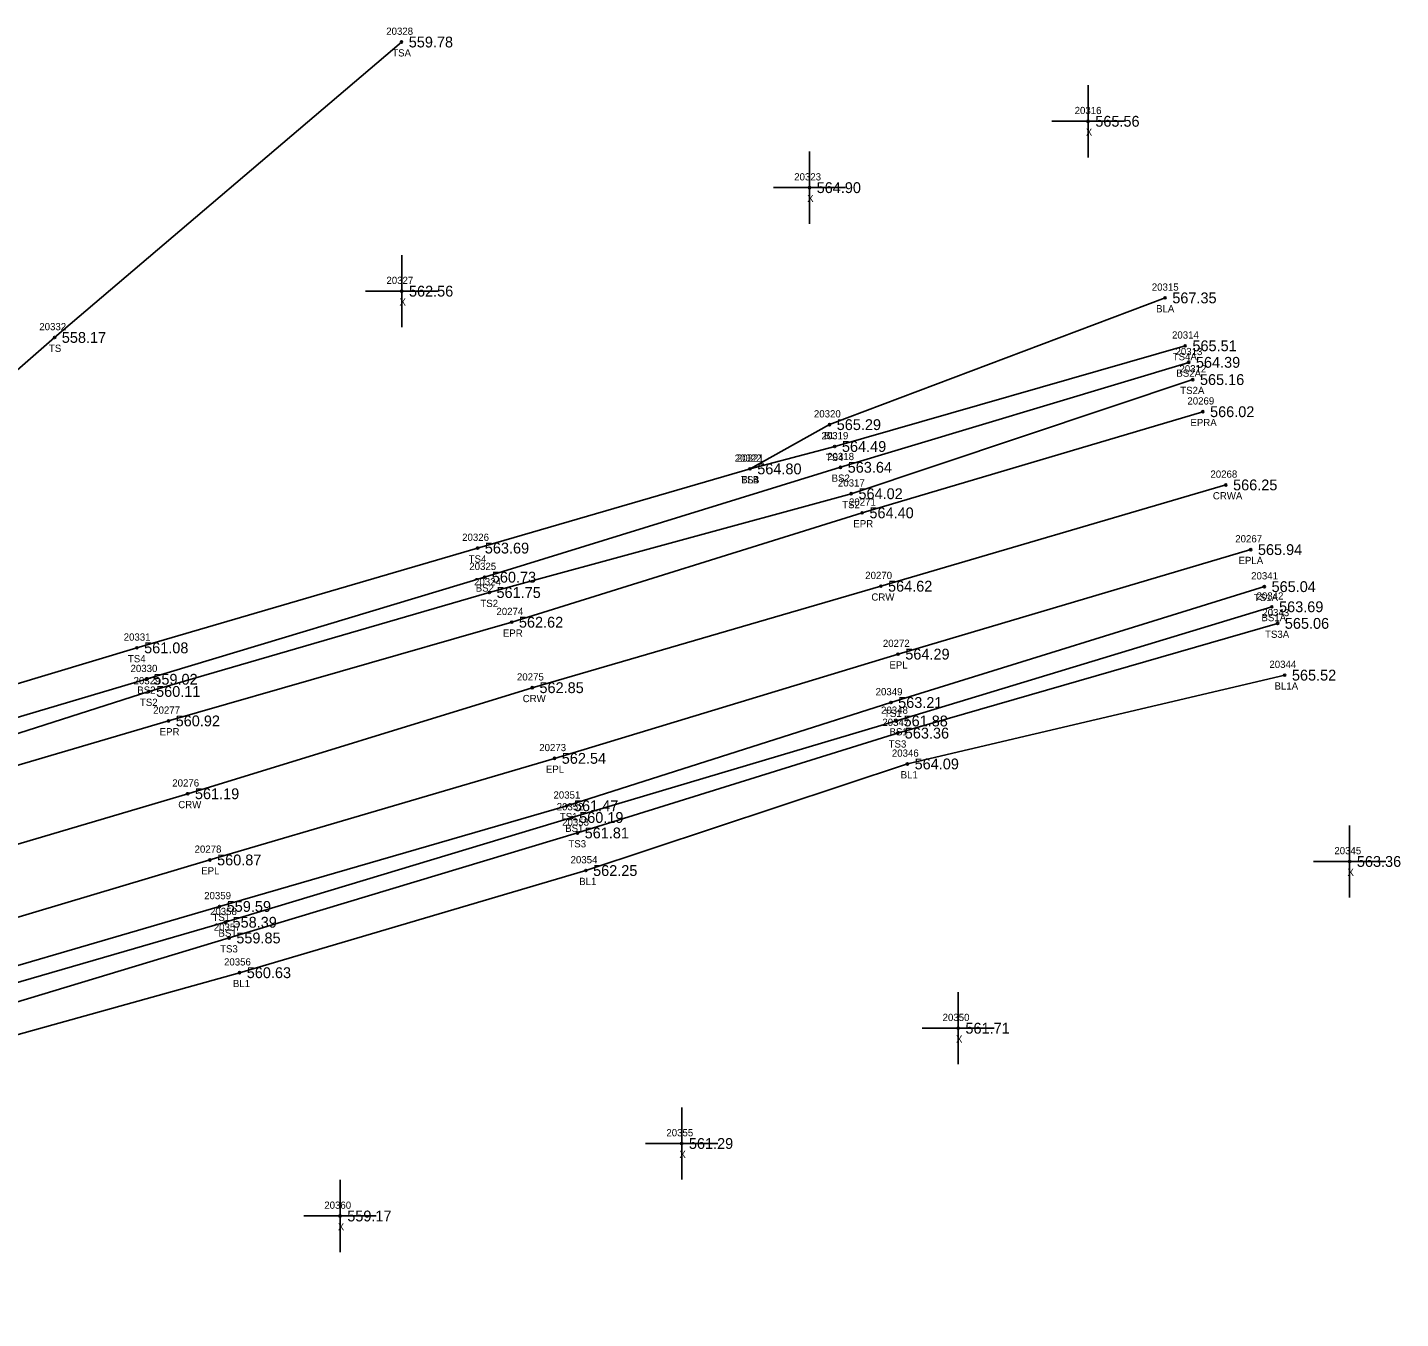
# Model space of a CAD drawing. Extents: x 1540443 to 1541844, y 887157 to 888162.
# Drawn here: x 1541653.6 to 1541843.8, y 887763.6 to 887942.4 of the extents above; entities that cross this region are included whole.
import ezdxf

# ---------------------------------------------------------------- set-up
doc = ezdxf.new("R2010")
doc.units = 0
for name, color, linetype in [('RD_DTM_BkLn1', 7, 'Continuous'), ('RD_DTM_BkLn2', 7, 'Continuous'), ('RD_DTM_BkLn_txCode', 7, 'Continuous'), ('RD_EX_Misc', 7, 'Continuous'), ('RD_EX_Misc_txCode', 7, 'Continuous'), ('RD_EX_Road', 7, 'Continuous'), ('RD_EX_Road_txCode', 7, 'Continuous'), ('RD_EX_TX_Misc_ELEV', 7, 'Continuous'), ('RD_EX_TX_Road_ELEV', 7, 'Continuous'), ('RD_HC_Survey_ELEV', 7, 'Continuous'), ('RD_HC_Survey_txCode', 7, 'Continuous'), ('RD_SMD_Locator', 7, 'Continuous')]:
    doc.layers.add(name, color=color, linetype=linetype)

msp = doc.modelspace()

# ---------------------------------------------------------------- linework, layer by layer
at = {"layer": 'RD_DTM_BkLn1'}
for points in [[(1541811.22, 887904.95), (1541764.73, 887887.39), (1541753.72, 887881.26)], [(1541819.64, 887879.04), (1541771.84, 887865.01), (1541723.55, 887850.95), (1541675.82, 887836.26), (1541627.89, 887822.08), (1541580.01, 887807.87), (1541531.93, 887793.38), (1541484.13, 887778.91), (1541435.66, 887765.21), (1541388.1, 887751.04), (1541339.55, 887736.89), (1541291.46, 887723.08), (1541243.5, 887708.82), (1541195.27, 887694.78), (1541169.43, 887686.85)], [(1541827.79, 887852.69), (1541775.52, 887840.39), (1541730.98, 887825.62), (1541683, 887811.47), (1541633.73, 887797.72), (1541590.59, 887782.42), (1541539.36, 887766.46)]]:
    msp.add_lwpolyline(points, dxfattribs=at)
at = {"layer": 'RD_DTM_BkLn2'}
for points in [[(1541705.44, 887940.39), (1541657.38, 887899.47), (1541615.37, 887862.76), (1541586.87, 887843.69), (1541555.2, 887844), (1541525.74, 887837.02), (1541487.41, 887823.68), (1541473.12, 887820.98), (1541413.13, 887806.68)], [(1541814.01, 887898.31), (1541765.45, 887884.36), (1541753.72, 887881.26), (1541715.98, 887870.29), (1541668.78, 887856.47), (1541621.42, 887842.24), (1541577.85, 887827.54), (1541526.45, 887812.7), (1541478.33, 887797.72), (1541429.46, 887781.77)], [(1541814.49, 887896.02), (1541766.25, 887881.48), (1541716.95, 887866.26), (1541670.06, 887852.12), (1541622.59, 887838.05), (1541578.09, 887825.05), (1541526.96, 887809.73), (1541478.59, 887795.12), (1541429.46, 887781.77), (1541395.42, 887775.23), (1541380.33, 887789.16)], [(1541815.05, 887893.63), (1541767.74, 887877.82), (1541717.6, 887864.13), (1541670.44, 887850.43), (1541623.55, 887835.4), (1541578.57, 887823.06), (1541527.24, 887806.39), (1541479.99, 887791.81), (1541430.31, 887778.05), (1541393.69, 887768.38), (1541380.33, 887789.16)], [(1541824.97, 887864.95), (1541773.24, 887848.9), (1541728.33, 887834.59), (1541680.22, 887820.65), (1541632.2, 887806.6), (1541586.15, 887794.2), (1541535.56, 887777.78), (1541490.03, 887763.87), (1541442.11, 887749.28), (1541414.74, 887732.66), (1541394.55, 887728.51), (1541346.01, 887715.56), (1541298.68, 887704.05), (1541256.52, 887687.99), (1541253.67, 887682.12), (1541204.18, 887671.81), (1541185.24, 887668.7), (1541173.43, 887674.53)], [(1541826.01, 887862.16), (1541773.99, 887846.34), (1541729.05, 887832.97), (1541681.03, 887818.46), (1541632.94, 887804.51), (1541587.44, 887789.41), (1541536.78, 887773.27), (1541491.06, 887758.08), (1541445.99, 887740.14), (1541416.24, 887728.45), (1541395.49, 887723.75), (1541347.04, 887711.22), (1541300.85, 887696.02), (1541261.64, 887680.26), (1541255.59, 887675.42), (1541206.42, 887663.07), (1541174, 887652.79)], [(1541826.81, 887859.86), (1541774.16, 887844.66), (1541729.81, 887830.83), (1541681.55, 887816.28), (1541633.12, 887801.68), (1541588.74, 887788.35), (1541537.56, 887771.08), (1541491.43, 887756.24), (1541446.51, 887737.74), (1541416.24, 887728.45)]]:
    msp.add_lwpolyline(points, dxfattribs=at)
at = {"layer": 'RD_EX_Misc'}
for p, q in [((1541800.55, 887924.41), (1541800.55, 887934.41)), ((1541795.55, 887929.41), (1541805.55, 887929.41)), ((1541761.95, 887915.22), (1541761.95, 887925.22)), ((1541756.95, 887920.22), (1541766.95, 887920.22)), ((1541705.47, 887900.88), (1541705.47, 887910.88)), ((1541700.47, 887905.88), (1541710.47, 887905.88)), ((1541836.79, 887821.88), (1541836.79, 887831.88)), ((1541831.79, 887826.88), (1541841.79, 887826.88)), ((1541782.56, 887798.78), (1541782.56, 887808.78)), ((1541777.56, 887803.78), (1541787.56, 887803.78)), ((1541744.25, 887782.81), (1541744.25, 887792.81)), ((1541739.25, 887787.81), (1541749.25, 887787.81)), ((1541696.92, 887772.77), (1541696.92, 887782.77)), ((1541691.92, 887777.77), (1541701.92, 887777.77))]:
    msp.add_line(p, q, dxfattribs=at)
at = {"layer": 'RD_EX_Road'}
for points in [[(1541816.45, 887889.18), (1541769.26, 887875.17), (1541720.7, 887860.02), (1541673.15, 887846.35), (1541624.52, 887832.03), (1541577.1, 887817.68), (1541529.45, 887803.59), (1541481.09, 887788.89), (1541433.23, 887775.3), (1541384.84, 887760.56), (1541337.12, 887746.96), (1541288.35, 887732.65), (1541241.37, 887718.72), (1541192.23, 887703.89), (1541166.88, 887695.38)], [(1541823.08, 887870.08), (1541774.23, 887855.6), (1541726.64, 887841.16), (1541678.89, 887827.09), (1541630.15, 887812.57), (1541582.93, 887798.43), (1541534.59, 887784.1), (1541487.04, 887769.99), (1541438.64, 887755.66), (1541391.44, 887742.05), (1541342.36, 887727.48), (1541295.07, 887713.91), (1541246.74, 887699.66), (1541197.81, 887684.79), (1541172.48, 887676.63)]]:
    msp.add_lwpolyline(points, dxfattribs=at)
at = {"layer": 'RD_SMD_Locator'}
for centre in [(1541705.44, 887940.39), (1541800.55, 887929.41), (1541761.95, 887920.22), (1541705.47, 887905.88), (1541811.22, 887904.95), (1541657.38, 887899.47), (1541814.01, 887898.31), (1541814.49, 887896.02), (1541815.05, 887893.63), (1541816.45, 887889.18), (1541764.73, 887887.39), (1541765.45, 887884.36), (1541753.72, 887881.26), (1541753.72, 887881.26), (1541766.25, 887881.48), (1541819.64, 887879.04), (1541767.74, 887877.82), (1541769.26, 887875.17), (1541715.98, 887870.29), (1541823.08, 887870.08), (1541716.95, 887866.26), (1541771.84, 887865.01), (1541824.97, 887864.95), (1541717.6, 887864.13), (1541826.01, 887862.16), (1541720.7, 887860.02), (1541826.81, 887859.86), (1541668.78, 887856.47), (1541774.23, 887855.6), (1541670.06, 887852.12), (1541827.79, 887852.69), (1541670.44, 887850.43), (1541723.55, 887850.95), (1541773.24, 887848.9), (1541673.15, 887846.35), (1541773.99, 887846.34), (1541774.16, 887844.66), (1541726.64, 887841.16), (1541775.52, 887840.39), (1541675.82, 887836.26), (1541728.33, 887834.59), (1541729.05, 887832.97), (1541729.81, 887830.83), (1541678.89, 887827.09), (1541730.98, 887825.62), (1541836.79, 887826.88), (1541680.22, 887820.65), (1541681.03, 887818.46), (1541681.55, 887816.28), (1541683, 887811.47), (1541782.56, 887803.78), (1541744.25, 887787.81), (1541696.92, 887777.77)]:
    msp.add_circle(centre, 0.15, dxfattribs=at)

# ---------------------------------------------------------------- texts
at = {"layer": 'RD_DTM_BkLn_txCode'}
for s, p in [('20328', (1541703.32, 887941.39)), ('TSA', (1541704.15, 887938.39)), ('20315', (1541809.38, 887905.95)), ('BLA', (1541809.97, 887902.95)), ('20332', (1541655.26, 887900.47)), ('20314', (1541812.18, 887899.31)), ('TS', (1541656.59, 887897.47)), ('20313', (1541812.66, 887897.02)), ('TS4A', (1541812.28, 887896.31)), ('20312', (1541813.21, 887894.63)), ('BS2A', (1541812.78, 887894.02)), ('TS2A', (1541813.32, 887891.63)), ('20320', (1541762.57, 887888.39)), ('20319', (1541763.62, 887885.36)), ('BL', (1541763.97, 887885.39)), ('20322', (1541751.6, 887882.26)), ('20321', (1541751.89, 887882.26)), ('TS4', (1541764.21, 887882.36)), ('20318', (1541764.41, 887882.48)), ('BS2', (1541765.02, 887879.48)), ('TS4', (1541752.48, 887879.26)), ('BLB', (1541752.49, 887879.26)), ('20317', (1541765.9, 887878.82)), ('TS2', (1541766.49, 887875.82)), ('20326', (1541713.84, 887871.29)), ('TS4', (1541714.74, 887868.29)), ('20325', (1541714.83, 887867.26)), ('20324', (1541715.49, 887865.13)), ('BS2', (1541715.72, 887864.26)), ('20341', (1541823.14, 887865.95)), ('TS1A', (1541823.52, 887862.95)), ('20342', (1541823.89, 887863.16)), ('TS2', (1541716.36, 887862.13)), ('20343', (1541824.69, 887860.86)), ('BS1A', (1541824.57, 887860.16)), ('20331', (1541666.95, 887857.47)), ('TS3A', (1541825.07, 887857.86)), ('TS4', (1541667.54, 887854.47)), ('20330', (1541667.9, 887853.12)), ('20344', (1541825.67, 887853.69)), ('20329', (1541668.32, 887851.43)), ('BS2', (1541668.83, 887850.12)), ('20349', (1541771.12, 887849.9)), ('BL1A', (1541826.38, 887850.69)), ('TS2', (1541669.2, 887848.43)), ('20348', (1541771.87, 887847.34)), ('20347', (1541772.05, 887845.66)), ('TS1', (1541772.28, 887846.9)), ('BS1', (1541773.04, 887844.34)), ('TS3', (1541772.92, 887842.66)), ('20346', (1541773.37, 887841.39)), ('BL1', (1541774.59, 887838.39)), ('20351', (1541726.49, 887835.59)), ('20352', (1541726.94, 887833.97)), ('TS1', (1541727.37, 887832.59)), ('20353', (1541727.69, 887831.83)), ('BS1', (1541728.11, 887830.97)), ('TS3', (1541728.56, 887828.83)), ('20354', (1541728.86, 887826.62)), ('BL1', (1541730.06, 887823.62)), ('20359', (1541678.1, 887821.65)), ('20358', (1541678.91, 887819.46)), ('TS1', (1541679.25, 887818.65)), ('20357', (1541679.43, 887817.28)), ('BS1', (1541680.08, 887816.46)), ('TS3', (1541680.31, 887814.28)), ('20356', (1541680.85, 887812.47)), ('BL1', (1541682.08, 887809.47))]:
    msp.add_text(s, height=1, dxfattribs=at).set_placement(p)
at = {"layer": 'RD_EX_Misc_txCode'}
for s, p in [('20316', (1541798.69, 887930.41)), ('X', (1541800.24, 887927.41)), ('20323', (1541759.84, 887921.22)), ('X', (1541761.64, 887918.22)), ('20327', (1541703.35, 887906.88)), ('X', (1541705.16, 887903.88)), ('20345', (1541834.67, 887827.88)), ('X', (1541836.48, 887824.88)), ('20350', (1541780.4, 887804.78)), ('X', (1541782.25, 887801.78)), ('20355', (1541742.13, 887788.81)), ('X', (1541743.93, 887785.81)), ('20360', (1541694.74, 887778.77)), ('X', (1541696.61, 887775.77))]:
    msp.add_text(s, height=1, dxfattribs=at).set_placement(p)
at = {"layer": 'RD_EX_Road_txCode'}
for s, p in [('20269', (1541814.31, 887890.18)), ('EPRA', (1541814.73, 887887.18)), ('20271', (1541767.43, 887876.17)), ('EPR', (1541768.03, 887873.17)), ('20267', (1541820.94, 887871.08)), ('EPLA', (1541821.39, 887868.08)), ('20274', (1541718.59, 887861.02)), ('EPR', (1541719.48, 887858.02)), ('20272', (1541772.12, 887856.6)), ('EPL', (1541773.03, 887853.6)), ('20277', (1541671.04, 887847.35)), ('EPR', (1541671.93, 887844.35)), ('20273', (1541724.52, 887842.16)), ('EPL', (1541725.44, 887839.16)), ('20278', (1541676.77, 887828.09)), ('EPL', (1541677.69, 887825.09))]:
    msp.add_text(s, height=1, dxfattribs=at).set_placement(p)
at = {"layer": 'RD_EX_TX_Misc_ELEV'}
for s, p in [('559.78', (1541706.44, 887939.64)), ('565.56', (1541801.55, 887928.66)), ('564.90', (1541762.95, 887919.47)), ('562.56', (1541706.47, 887905.13)), ('567.35', (1541812.22, 887904.2)), ('558.17', (1541658.38, 887898.72)), ('565.51', (1541815.01, 887897.56)), ('564.39', (1541815.49, 887895.27)), ('565.16', (1541816.05, 887892.88)), ('565.29', (1541765.73, 887886.64)), ('564.49', (1541766.45, 887883.61)), ('563.64', (1541767.25, 887880.73)), ('564.80', (1541754.72, 887880.51)), ('564.80', (1541754.72, 887880.51)), ('564.02', (1541768.74, 887877.07)), ('563.69', (1541716.98, 887869.54)), ('560.73', (1541717.95, 887865.51)), ('565.04', (1541825.97, 887864.2)), ('561.75', (1541718.6, 887863.38)), ('563.69', (1541827.01, 887861.41)), ('565.06', (1541827.81, 887859.11)), ('561.08', (1541669.78, 887855.72)), ('559.02', (1541671.06, 887851.37)), ('565.52', (1541828.79, 887851.94)), ('560.11', (1541671.44, 887849.68)), ('563.21', (1541774.24, 887848.15)), ('561.88', (1541774.99, 887845.59)), ('563.36', (1541775.16, 887843.91)), ('564.09', (1541776.52, 887839.64)), ('561.47', (1541729.33, 887833.84)), ('560.19', (1541730.05, 887832.22)), ('561.81', (1541730.81, 887830.08)), ('563.36', (1541837.79, 887826.13)), ('562.25', (1541731.98, 887824.87)), ('559.59', (1541681.22, 887819.9)), ('558.39', (1541682.03, 887817.71)), ('559.85', (1541682.55, 887815.53)), ('560.63', (1541684, 887810.72)), ('561.71', (1541783.56, 887803.03)), ('561.29', (1541745.25, 887787.06)), ('559.17', (1541697.92, 887777.02))]:
    msp.add_text(s, height=1.5, dxfattribs=at).set_placement(p)
at = {"layer": 'RD_EX_TX_Road_ELEV'}
for s, p in [('566.02', (1541817.45, 887888.43)), ('564.40', (1541770.26, 887874.42)), ('565.94', (1541824.08, 887869.33)), ('562.62', (1541721.7, 887859.27)), ('564.29', (1541775.23, 887854.85)), ('560.92', (1541674.15, 887845.6)), ('562.54', (1541727.64, 887840.41)), ('560.87', (1541679.89, 887826.34))]:
    msp.add_text(s, height=1.5, dxfattribs=at).set_placement(p)
at = {"layer": 'RD_HC_Survey_ELEV'}
for s, p in [('566.25', (1541820.64, 887878.29)), ('564.62', (1541772.84, 887864.26)), ('562.85', (1541724.55, 887850.2)), ('561.19', (1541676.82, 887835.51))]:
    msp.add_text(s, height=1.5, dxfattribs=at).set_placement(p)
at = {"layer": 'RD_HC_Survey_txCode'}
for s, p in [('20268', (1541817.5, 887880.04)), ('CRWA', (1541817.84, 887877.04)), ('20270', (1541769.68, 887866.01)), ('CRW', (1541770.53, 887863.01)), ('20275', (1541721.43, 887851.95)), ('CRW', (1541722.23, 887848.95)), ('20276', (1541673.68, 887837.26)), ('CRW', (1541674.51, 887834.26))]:
    msp.add_text(s, height=1, dxfattribs=at).set_placement(p)

doc.saveas('drawing.dxf')
